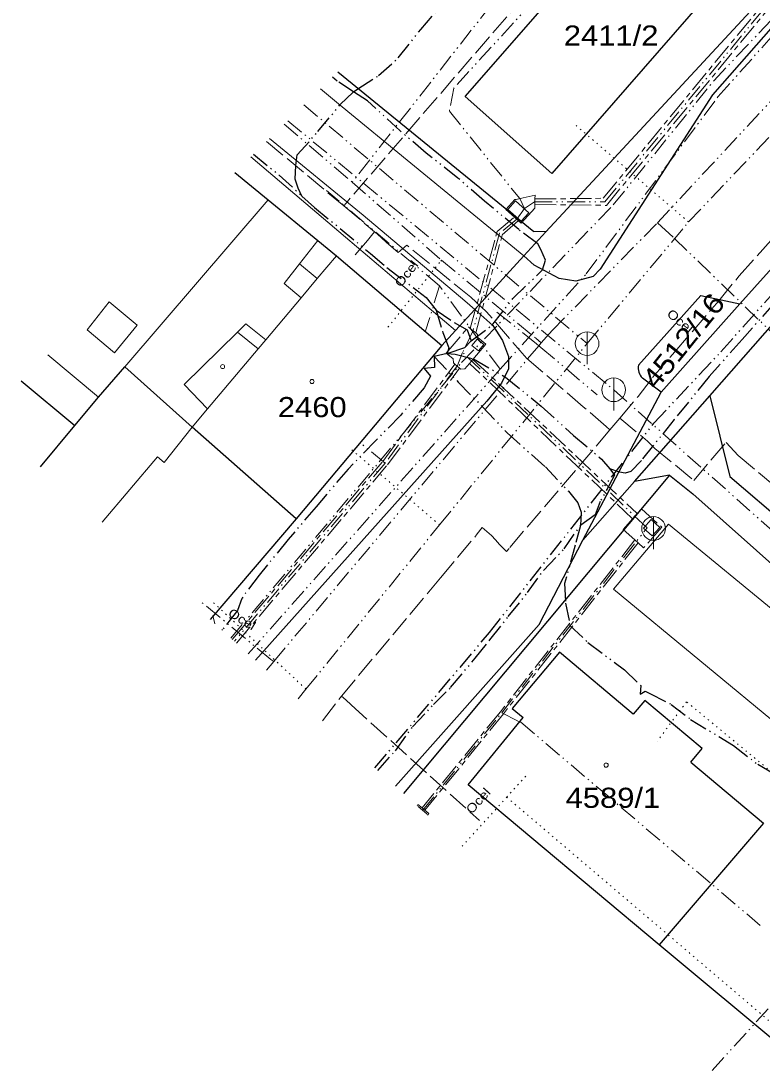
# Model space of a CAD drawing. Extents: x -683947 to -683762, y -1065756 to -1065543.
# Drawn here: x -683946.8 to -683884.2, y -1065742.7 to -1065654 of the extents above; entities that cross this region are included whole.
import ezdxf
from ezdxf.enums import TextEntityAlignment as Align

# ---------------------------------------------------------------- set-up
doc = ezdxf.new("R2010")
doc.units = 0
doc.header["$LTSCALE"] = 0.3
for name, pattern in [('DASH_DOUBLE_DOT', [9.2, 5, -1.2, 0.3, -1.2, 0.3, -1.2]), ('DOTTED', [1.5, 0.3, -1.2]), ('LONG_DASH_SHORT_DASH', [9.9, 6, -1.2, 1.5, -1.2]), ('LONG_DASHED', [7.5, 6, -1.5])]:
    doc.linetypes.add(name, pattern=pattern)
for name, color, linetype, lineweight in [('1', 7, 'Continuous', 25), ('10', 7, 'Continuous', 13), ('26', 7, 'LONG_DASH_SHORT_DASH', 13), ('31', 7, 'DASH_DOUBLE_DOT', 13), ('35', 7, 'LONG_DASHED', 13), ('36', 7, 'DASH_DOUBLE_DOT', 25), ('4', 7, 'Continuous', 13), ('41', 7, 'DASH_DOUBLE_DOT', 13), ('46', 7, 'DASH_DOUBLE_DOT', 13), ('5', 7, 'Continuous', 13), ('50', 7, 'LONG_DASHED', 13), ('51', 7, 'DOTTED', 13)]:
    doc.layers.add(name, color=color, linetype=linetype, lineweight=lineweight)
doc.layers.add('19', color=7, linetype='Continuous')
doc.layers.add('2', color=7, linetype='Continuous')

msp = doc.modelspace()

# ---------------------------------------------------------------- linework, layer by layer
at = {"layer": '1'}
for p, q in [((-683861.55, -1065627.6), (-683902.49, -1065671.82)), ((-683909.31, -1065660.38), (-683892.56, -1065641.22)), ((-683888.65, -1065685.67), (-683863.13, -1065656.59)), ((-683886.11, -1065677.9), (-683867.65, -1065657.22)), ((-683920.071, -1065658.308), (-683903.51, -1065671.79)), ((-683901.98, -1065666.88), (-683909.31, -1065660.38)), ((-683928.769, -1065666.79), (-683925.96, -1065669.1)), ((-683925.96, -1065669.1), (-683921.76, -1065672.55)), ((-683921.76, -1065672.55), (-683920.19, -1065673.84)), ((-683902.49, -1065671.82), (-683904.35, -1065673.85)), ((-683902.49, -1065671.82), (-683903.51, -1065671.79)), ((-683920.19, -1065673.84), (-683911.29, -1065681.42)), ((-683904.35, -1065673.85), (-683908.5, -1065678.37)), ((-683894.68, -1065683.08), (-683889.41, -1065677.19)), ((-683892.77, -1065685.36), (-683886.11, -1065677.9)), ((-683889.41, -1065677.19), (-683886.11, -1065677.9)), ((-683911.29, -1065681.42), (-683923.59, -1065696.05)), ((-683940.28, -1065685.79), (-683938.07, -1065683.21)), ((-683938.07, -1065683.21), (-683932.38, -1065688.32)), ((-683892.77, -1065685.36), (-683894.34, -1065684.17)), ((-683946.835, -1065684.406), (-683942.3, -1065688.19)), ((-683906.24, -1065684.61), (-683907.49, -1065686.13)), ((-683942.3, -1065688.19), (-683940.28, -1065685.79)), ((-683899.37, -1065697.87), (-683892.77, -1065685.36)), ((-683888.65, -1065685.67), (-683886.97, -1065692.49)), ((-683907.49, -1065686.13), (-683927.033, -1065708.006)), ((-683945.184, -1065691.663), (-683942.3, -1065688.19)), ((-683923.59, -1065696.05), (-683932.38, -1065688.32)), ((-683892.04, -1065692.36), (-683914.526, -1065719.266)), ((-683892.04, -1065692.36), (-683890.08, -1065693.94)), ((-683886.97, -1065692.49), (-683871.07, -1065706.07)), ((-683890.08, -1065693.94), (-683873.4, -1065708.83)), ((-683923.59, -1065696.05), (-683930.843, -1065704.575)), ((-683903.05, -1065704.98), (-683899.37, -1065697.87)), ((-683903.05, -1065704.98), (-683915.21, -1065718.651)), ((-683901.35, -1065707.34), (-683905.33, -1065712.09)), ((-683905.33, -1065712.09), (-683904.41, -1065712.86)), ((-683909.06, -1065718.53), (-683904.41, -1065712.86)), ((-683892.92, -1065732.04), (-683909.06, -1065718.53)), ((-683881.3, -1065741.76), (-683892.92, -1065732.04))]:
    msp.add_line(p, q, dxfattribs=at)
for points in [[(-683859.58, -1065630.9), (-683875.3, -1065645.28), (-683888.43, -1065660.25), (-683897.91, -1065674.98), (-683898.51, -1065675.59)], [(-683892.56, -1065641.22), (-683885.21, -1065647.62), (-683901.98, -1065666.88)], [(-683901.37, -1065675.77), (-683903.48, -1065674.63), (-683904.35, -1065673.85)], [(-683898.51, -1065675.59), (-683899.97, -1065675.97), (-683901.37, -1065675.77)], [(-683908.5, -1065678.37), (-683910.12, -1065680.14), (-683911.29, -1065681.42)], [(-683908.5, -1065678.37), (-683906.98, -1065679.72), (-683906.15, -1065681), (-683905.64, -1065682.34), (-683905.65, -1065683.39), (-683906.24, -1065684.61)], [(-683892.04, -1065692.36), (-683895.01, -1065692.91), (-683888.65, -1065685.67)], [(-683890.26, -1065716.63), (-683889.29, -1065715.47), (-683894.14, -1065711.41), (-683895.11, -1065712.56), (-683901.35, -1065707.34)], [(-683890.26, -1065716.63), (-683884.1, -1065721.78), (-683892.92, -1065732.04)]]:
    msp.add_lwpolyline(points, dxfattribs=at)
msp.add_arc((-683893.488, -1065683.306), 1.213, 169.25356, 225.39461, dxfattribs=at)
at = {"layer": '10'}
for p, q in [((-683899.015, -1065680.256), (-683899.015, -1065683.004)), ((-683896.766, -1065684.156), (-683896.766, -1065686.904)), ((-683893.397, -1065695.876), (-683893.397, -1065698.624))]:
    msp.add_line(p, q, dxfattribs=at)
for centre in [(-683899.015, -1065681.258), (-683896.766, -1065685.158), (-683893.397, -1065696.878)]:
    msp.add_circle(centre, 1, dxfattribs=at)
at = {"layer": '26'}
for p, q in [((-683895.17, -1065696.07), (-683908.94, -1065682.93)), ((-683908.66, -1065682.59), (-683894.78, -1065695.62))]:
    msp.add_line(p, q, dxfattribs=at)
for points in [[(-683903.42, -1065669.04), (-683897.66, -1065668.98), (-683878.7, -1065645.97), (-683862.91, -1065630.67)], [(-683903.43, -1065669.5), (-683897.38, -1065669.58), (-683878.26, -1065646.37), (-683862.48, -1065631.07)], [(-683908.88, -1065679.98), (-683906.62, -1065671.79), (-683905.16, -1065670.58)], [(-683908.42, -1065680.36), (-683906.18, -1065672.07), (-683904.82, -1065670.88)], [(-683928.985, -1065706.248), (-683916.28, -1065691.21), (-683910.18, -1065682.99)], [(-683928.632, -1065706.566), (-683915.88, -1065691.51), (-683909.78, -1065683.32)], [(-683894.97, -1065697.85), (-683906.34, -1065712.36), (-683912.95, -1065720.49)], [(-683894.7, -1065698.09), (-683906.08, -1065712.54), (-683912.72, -1065720.68)], [(-683913.381, -1065720.298), (-683913.3, -1065720.2), (-683912.95, -1065720.49), (-683912.72, -1065720.68), (-683912.37, -1065720.96), (-683912.487, -1065721.102)], [(-683913.289, -1065720.381), (-683913.28, -1065720.37), (-683912.54, -1065720.98), (-683912.576, -1065721.023)]]:
    msp.add_lwpolyline(points, dxfattribs=at)
for points in [[(-683905.88, -1065669.94), (-683905.12, -1065669.09), (-683905, -1065669.07), (-683904.41, -1065668.94), (-683903.41, -1065668.73), (-683903.42, -1065669.04), (-683903.43, -1065669.5), (-683903.44, -1065669.81), (-683904.58, -1065671.09), (-683904.82, -1065670.88), (-683905.16, -1065670.58)], [(-683905.71, -1065669.92), (-683905.07, -1065669.2), (-683903.95, -1065670.2), (-683904.59, -1065670.92)], [(-683910.91, -1065682.06), (-683909.04, -1065679.84), (-683908.88, -1065679.98), (-683908.42, -1065680.36), (-683908.27, -1065680.49), (-683908.24, -1065680.75), (-683907.58, -1065681.31), (-683908.66, -1065682.59), (-683908.94, -1065682.93), (-683909.33, -1065683.39), (-683909.67, -1065683.42), (-683909.78, -1065683.32), (-683910.18, -1065682.99), (-683910.3, -1065682.89), (-683910.32, -1065682.55)], [(-683908.74, -1065681.41), (-683908.29, -1065680.87), (-683907.75, -1065681.32), (-683908.2, -1065681.86)], [(-683895.97, -1065696.96), (-683895.17, -1065696.07), (-683894.78, -1065695.62), (-683894.43, -1065695.23), (-683892.7, -1065696.77), (-683894.24, -1065698.51), (-683894.7, -1065698.09), (-683894.97, -1065697.85)], [(-683894.25, -1065696.84), (-683893.61, -1065696.12), (-683892.87, -1065696.78), (-683893.51, -1065697.5)]]:
    msp.add_lwpolyline(points, close=True, dxfattribs=at)
at = {"layer": '31'}
for p, q in [((-683911.47, -1065676.39), (-683921.03, -1065668.33)), ((-683904.7, -1065669), (-683904.31, -1065669.83)), ((-683911.47, -1065676.39), (-683912.69, -1065680.27)), ((-683929.105, -1065706.14), (-683914.84, -1065689.19)), ((-683916.08, -1065691.36), (-683918.21, -1065689.6)), ((-683916.08, -1065691.36), (-683928.808, -1065706.407)), ((-683930.456, -1065704.923), (-683930.63, -1065704.22)), ((-683912.917, -1065720.715), (-683906.23, -1065712.46))]:
    msp.add_line(p, q, dxfattribs=at)
for points in [[(-683906.37, -1065683.43), (-683899.08, -1065675.36), (-683887.96, -1065660.41), (-683873.71, -1065644.44), (-683851.65, -1065622.08)], [(-683914.84, -1065689.19), (-683909.62, -1065682.86), (-683896.8, -1065669.54), (-683888.32, -1065659.06), (-683854.06, -1065622.89)], [(-683904.31, -1065669.83), (-683903.47, -1065669.28), (-683897.52, -1065669.28), (-683878.48, -1065646.17), (-683862.67, -1065630.88), (-683861.88, -1065629.98)], [(-683902.77, -1065652.64), (-683903.37, -1065652.11), (-683910.28, -1065659.68), (-683910.65, -1065661.62), (-683904.7, -1065669)], [(-683904.31, -1065669.83), (-683904.96, -1065670.74), (-683906.4, -1065671.93), (-683908.65, -1065680.16), (-683909.53, -1065682)], [(-683927.632, -1065707.466), (-683906.37, -1065683.43), (-683911.47, -1065676.39)], [(-683909.53, -1065682), (-683909.96, -1065683.12), (-683916.08, -1065691.36)], [(-683906.23, -1065712.46), (-683893.95, -1065696.83), (-683909.53, -1065682)], [(-683906.23, -1065712.46), (-683904.86, -1065713.15), (-683904.61, -1065713.25), (-683884.21, -1065730.56)]]:
    msp.add_lwpolyline(points, dxfattribs=at)
at = {"layer": '35'}
for p, q in [((-683893.079, -1065671.05), (-683891.662, -1065672.348)), ((-683902.899, -1065681.197), (-683901.977, -1065680.16)), ((-683903.099, -1065681.435), (-683903.297, -1065681.268)), ((-683903.099, -1065681.435), (-683902.899, -1065681.197)), ((-683903.099, -1065681.435), (-683902.915, -1065681.582)), ((-683897.08, -1065688.55), (-683896.24, -1065687.55))]:
    msp.add_line(p, q, dxfattribs=at)
for points in [[(-683896.24, -1065687.55), (-683894.71, -1065685.72), (-683893.48, -1065684.13), (-683891.61, -1065681.955), (-683887.89, -1065677.63), (-683886.16, -1065675.53), (-683853.44, -1065639.1), (-683848.45, -1065633.59), (-683843.114, -1065627.22), (-683843.08, -1065627.18), (-683831.4, -1065614.21), (-683820.06, -1065601.41), (-683812.91, -1065593.55), (-683807.75, -1065587.62), (-683793.84, -1065572.21), (-683791.969, -1065570.179), (-683790.708, -1065568.809), (-683790.074, -1065568.129)], [(-683899.923, -1065646.829), (-683919.379, -1065669.399), (-683919.57, -1065669.63)], [(-683926.089, -1065664.176), (-683919.57, -1065669.63), (-683916.96, -1065671.81), (-683916.76, -1065671.99), (-683915.98, -1065672.7)], [(-683897.08, -1065688.55), (-683897.39, -1065688.26), (-683899.337, -1065686.594), (-683904.1, -1065682.52), (-683907.51, -1065678.57), (-683908.84, -1065677.34), (-683914.24, -1065672.94), (-683914.98, -1065673.56), (-683915.98, -1065672.7)], [(-683903.347, -1065680.808), (-683903.13, -1065680.988), (-683902.899, -1065681.197)], [(-683896.24, -1065687.55), (-683893.9, -1065689.5), (-683893.29, -1065690.11), (-683890.01, -1065692.81), (-683887.28, -1065689.61)], [(-683897.08, -1065688.55), (-683905.61, -1065698.57), (-683905.809, -1065698.829), (-683906.41, -1065698.24), (-683906.75, -1065697.83), (-683907.09, -1065697.48), (-683907.872, -1065696.805), (-683908.29, -1065697.34)], [(-683887.28, -1065689.61), (-683886.26, -1065690.7), (-683864.21, -1065709.26), (-683855.82, -1065715.78), (-683853.98, -1065717.41), (-683853.87, -1065717.71), (-683852.4, -1065718.86), (-683851.92, -1065719.26), (-683851.43, -1065719.6), (-683848.68, -1065722.04), (-683848.11, -1065722.47), (-683847.23, -1065722.66), (-683845.45, -1065722.12), (-683843.4, -1065722), (-683841.012, -1065724.081)], [(-683921.359, -1065713.115), (-683919.76, -1065711.03), (-683911.398, -1065701.049), (-683908.29, -1065697.34)]]:
    msp.add_lwpolyline(points, dxfattribs=at)
at = {"layer": '36', "lineweight": 13}
for p, q in [((-683924.603, -1065662.727), (-683918.858, -1065667.62)), ((-683901.977, -1065680.16), (-683893.079, -1065671.05)), ((-683891.662, -1065672.348), (-683883.388, -1065680.331)), ((-683903.297, -1065681.268), (-683906.929, -1065678.365)), ((-683902.915, -1065681.582), (-683898.163, -1065685.59))]:
    msp.add_line(p, q, dxfattribs=at)
at = {"layer": '36'}
msp.add_line((-683910.84, -1065682.1), (-683911.93, -1065682.36), dxfattribs=at)
at = {"layer": '36', "lineweight": 13}
for points in [[(-683870.287, -1065612.435), (-683879.753, -1065621.49), (-683887.014, -1065628.435), (-683896.789, -1065639.476), (-683918.858, -1065667.62)], [(-683893.079, -1065671.05), (-683871.468, -1065647.886), (-683863.976, -1065639.798), (-683853.405, -1065628.437)], [(-683918.858, -1065667.62), (-683911.31, -1065674.209), (-683903.347, -1065680.808)], [(-683926.101, -1065708.845), (-683925.48, -1065708.115), (-683903.099, -1065681.435)]]:
    msp.add_lwpolyline(points, dxfattribs=at)
at = {"layer": '36'}
for points in [[(-683918.74, -1065659.99), (-683918.38, -1065659.72), (-683916.63, -1065658.62), (-683914.98, -1065657.12), (-683913.07, -1065654.72), (-683910.37, -1065651.57), (-683908.32, -1065648.79), (-683907.17, -1065647.97), (-683906.37, -1065647.66)], [(-683861.4, -1065652.77), (-683863.72, -1065655.58), (-683866.45, -1065658.77), (-683869.22, -1065661.92), (-683871.81, -1065664.82), (-683874.67, -1065668.11), (-683877.93, -1065671.8), (-683880.49, -1065674.63), (-683881.78, -1065676.2), (-683883.21, -1065677.83), (-683885.92, -1065680.91), (-683888.71, -1065684.04), (-683891.65, -1065687.67), (-683894.43, -1065691.13), (-683895.32, -1065692.06), (-683895.79, -1065692.2), (-683896.27, -1065692.12), (-683897.08, -1065691.84)], [(-683918.74, -1065659.99), (-683920.12, -1065659.08), (-683920.517, -1065658.743)], [(-683923.1, -1065668.8), (-683923.43, -1065668.13), (-683923.68, -1065667.36), (-683923.61, -1065666.21), (-683923.5, -1065665.32), (-683921.75, -1065663.35), (-683919.86, -1065661.05), (-683918.74, -1065659.99)], [(-683908.8, -1065681.02), (-683907.06, -1065679.72), (-683905.29, -1065677.46), (-683902.78, -1065675.02), (-683902.52, -1065674.2), (-683902.92, -1065673.32), (-683903.17, -1065672.83), (-683904.78, -1065671.63), (-683907.67, -1065669.22), (-683909.92, -1065667.28), (-683912.6, -1065665.17), (-683914.81, -1065663.28), (-683917.56, -1065660.75), (-683918.74, -1065659.99)], [(-683927.191, -1065665.25), (-683925.02, -1065667.04), (-683923.1, -1065668.8)], [(-683923.1, -1065668.8), (-683922.04, -1065669.77), (-683919.88, -1065671.52), (-683917.31, -1065673.65), (-683915.92, -1065674.84), (-683912.62, -1065677.35), (-683911.77, -1065678.44)], [(-683911.77, -1065678.44), (-683911.2, -1065680.32), (-683910.7, -1065681.62), (-683910.84, -1065682.1)], [(-683911.77, -1065678.44), (-683910.24, -1065679.47), (-683909.14, -1065680.09), (-683908.8, -1065681.02)], [(-683908.8, -1065681.02), (-683909.36, -1065681.62), (-683910.84, -1065682.1)], [(-683911.93, -1065682.36), (-683911.91, -1065683.29), (-683912.77, -1065683.36)], [(-683911.93, -1065682.36), (-683909.91, -1065684.51), (-683907.87, -1065686.57), (-683905.78, -1065688.79), (-683902.54, -1065691.67), (-683900.59, -1065693.73), (-683899.79, -1065694.71), (-683899.52, -1065695.49), (-683899.58, -1065696.62)], [(-683910.84, -1065682.1), (-683910.17, -1065682.14), (-683908.61, -1065682.55), (-683905.9, -1065684.1)], [(-683912.77, -1065683.36), (-683912.23, -1065684), (-683912.79, -1065685), (-683914.78, -1065687.32), (-683916.85, -1065689.43), (-683919.21, -1065691.86), (-683921.9, -1065695.04), (-683924.26, -1065697.8), (-683926.72, -1065700.81), (-683928.19, -1065702.79), (-683928.54, -1065703.82), (-683929.82, -1065705.41), (-683929.867, -1065705.454)], [(-683905.9, -1065684.1), (-683902.9, -1065686.53), (-683900.15, -1065689.02), (-683897.8, -1065691.02), (-683897.08, -1065691.84)], [(-683897.08, -1065691.84), (-683896.7, -1065692.36), (-683897.9, -1065694.6), (-683898.33, -1065695.72), (-683899.58, -1065696.62)], [(-683916.688, -1065717.32), (-683915.21, -1065715.65), (-683913.75, -1065713.63), (-683911.98, -1065711.74), (-683910.54, -1065710.3), (-683908.46, -1065707.82), (-683907.24, -1065706.29), (-683905.67, -1065704.32), (-683904.04, -1065702.29), (-683902.71, -1065700.42), (-683900.95, -1065698.6), (-683899.58, -1065696.62)], [(-683899.58, -1065696.62), (-683900.02, -1065698.29), (-683900.91, -1065701.52), (-683900.84, -1065703.19), (-683900.46, -1065705.06), (-683898.95, -1065706.51), (-683895.86, -1065708.82), (-683894.48, -1065710.15), (-683894.53, -1065710.88)], [(-683894.53, -1065710.88), (-683894.11, -1065710.62), (-683893.72, -1065710.81), (-683891.9, -1065711.74), (-683890.27, -1065713.01), (-683886.64, -1065715.22), (-683884.59, -1065716.8), (-683882.93, -1065717.78), (-683879.86, -1065720.75), (-683879.93, -1065721.17), (-683880.1, -1065721.68)]]:
    msp.add_lwpolyline(points, dxfattribs=at)
at = {"layer": '4'}
for p, q in [((-683921.524, -1065659.725), (-683920.01, -1065660.99)), ((-683920.01, -1065660.99), (-683913.89, -1065666)), ((-683917.92, -1065670.42), (-683925.833, -1065663.926)), ((-683927.421, -1065665.475), (-683919.42, -1065672.26)), ((-683913.89, -1065666), (-683904.35, -1065673.85)), ((-683925.96, -1065669.1), (-683938.07, -1065683.21)), ((-683909.35, -1065677.65), (-683917.92, -1065670.42)), ((-683923.3, -1065674.52), (-683921.76, -1065672.55)), ((-683919.42, -1065672.26), (-683910.12, -1065680.14)), ((-683921.81, -1065675.77), (-683920.19, -1065673.84)), ((-683923.3, -1065674.52), (-683921.81, -1065675.77)), ((-683923.18, -1065677.39), (-683921.81, -1065675.77)), ((-683908.5, -1065678.37), (-683909.35, -1065677.65)), ((-683938.94, -1065682.03), (-683937.03, -1065679.71)), ((-683928.54, -1065680.28), (-683927.83, -1065679.58)), ((-683927.83, -1065679.58), (-683926.16, -1065680.93)), ((-683941.25, -1065680.08), (-683938.94, -1065682.03)), ((-683933.06, -1065684.72), (-683928.54, -1065680.28)), ((-683928.54, -1065680.28), (-683926.8, -1065681.69)), ((-683944.581, -1065682.207), (-683940.28, -1065685.79)), ((-683931.07, -1065686.76), (-683926.8, -1065681.69)), ((-683932.38, -1065688.32), (-683934.75, -1065691.29)), ((-683935.3, -1065690.83), (-683939.99, -1065696.339)), ((-683934.75, -1065691.29), (-683935.3, -1065690.83)), ((-683899.37, -1065697.87), (-683895.01, -1065692.91)), ((-683896.78, -1065702.01), (-683892.15, -1065696.52)), ((-683892.15, -1065696.52), (-683860.6, -1065722.41)), ((-683862.22, -1065730.6), (-683896.78, -1065702.01))]:
    msp.add_line(p, q, dxfattribs=at)
for points in [[(-683926.8, -1065681.69), (-683926.16, -1065680.93), (-683923.18, -1065677.39), (-683924.61, -1065676.19), (-683923.3, -1065674.52)], [(-683937.03, -1065679.71), (-683939.38, -1065677.72), (-683941.25, -1065680.08)], [(-683932.38, -1065688.32), (-683931.07, -1065686.76), (-683933.06, -1065684.72)]]:
    msp.add_lwpolyline(points, dxfattribs=at)
at = {"layer": '41', "lineweight": 25}
msp.add_line((-683916.932, -1065717.101), (-683907.26, -1065705.67), dxfattribs=at)
at = {"layer": '41'}
msp.add_line((-683883.719, -1065737.449), (-683888.487, -1065742.712), dxfattribs=at)
at = {"layer": '41', "lineweight": 25}
msp.add_lwpolyline([(-683907.26, -1065705.67), (-683893.37, -1065687.98), (-683887.71, -1065681.96), (-683876.81, -1065669.67), (-683869.01, -1065660.17), (-683861.43, -1065651.54), (-683852.89, -1065642.04), (-683845.02, -1065633.03), (-683836.31, -1065623.45), (-683820.34, -1065605.7), (-683789.54, -1065571.05), (-683781.76, -1065562.31), (-683777.124, -1065557.504)], dxfattribs=at)
at = {"layer": '46'}
for p, q in [((-683922.929, -1065661.095), (-683899.015, -1065681.258)), ((-683924.295, -1065662.427), (-683896.766, -1065685.158))]:
    msp.add_line(p, q, dxfattribs=at)
for points in [[(-683899.015, -1065681.258), (-683890.444, -1065670.977), (-683876.643, -1065656.48)], [(-683923.423, -1065711.256), (-683922.766, -1065710.45), (-683911.475, -1065696.572), (-683899.015, -1065681.258)], [(-683896.766, -1065685.158), (-683883.356, -1065697.074), (-683851.577, -1065725.125)]]:
    msp.add_lwpolyline(points, dxfattribs=at)
at = {"layer": '5'}
for centre in [(-683929.807, -1065683.199), (-683922.247, -1065684.459), (-683897.407, -1065716.869)]:
    msp.add_circle(centre, 0.175, dxfattribs=at)
at = {"layer": '50'}
for points in [[(-683918.596, -1065673.767), (-683917.57, -1065672.539), (-683917.214, -1065672.112), (-683916.96, -1065671.81)], [(-683919.76, -1065711.03), (-683919.402, -1065711.366), (-683918.95, -1065711.79), (-683908.11, -1065721.54)]]:
    msp.add_lwpolyline(points, dxfattribs=at)
at = {"layer": '51'}
for p, q in [((-683890.444, -1065670.977), (-683900.076, -1065662.719)), ((-683911.475, -1065696.572), (-683919.15, -1065690.011)), ((-683922.766, -1065710.45), (-683930.652, -1065703.062)), ((-683905.808, -1065719.58), (-683904.164, -1065717.767)), ((-683909.57, -1065723.728), (-683905.808, -1065719.58))]:
    msp.add_line(p, q, dxfattribs=at)
for points in [[(-683911.31, -1065674.209), (-683911.471, -1065674.404), (-683915.999, -1065680.077)], [(-683875.957, -1065723.621), (-683890.608, -1065711.528), (-683893.1, -1065714.852)], [(-683905.808, -1065719.58), (-683882.889, -1065739.117), (-683881.78, -1065737.682)]]:
    msp.add_lwpolyline(points, dxfattribs=at)
at = {"layer": '51', "linetype": 'DASH_DOUBLE_DOT'}
msp.add_lwpolyline([(-683925.48, -1065708.115), (-683925.727, -1065707.946), (-683931.582, -1065703.106)], dxfattribs=at)

# ---------------------------------------------------------------- texts
at = {"layer": '19', "width": 1.2}
for rotation, p in [(51.65, (-683914.746, -1065676.559)), (319.89, (-683892.342, -1065678.852)), (328.2, (-683929.413, -1065704.213)), (47.79, (-683908.766, -1065721.056))]:
    msp.add_text('Ocel ', height=0.75, rotation=rotation, dxfattribs=at).set_placement(p)
at = {"layer": '2', "width": 1.15}
for s, p in [('2411/2', (-683900.98, -1065656.08)), ('2460', (-683925.14, -1065687.47)), ('4589/1', (-683900.83, -1065720.48))]:
    msp.add_text(s, height=1.7, dxfattribs=at).set_placement(p)
msp.add_text('4512/16', height=1.7, rotation=51.22, dxfattribs=at).set_placement((-683890.216, -1065681.554), align=Align.CENTER)

doc.saveas('drawing.dxf')
